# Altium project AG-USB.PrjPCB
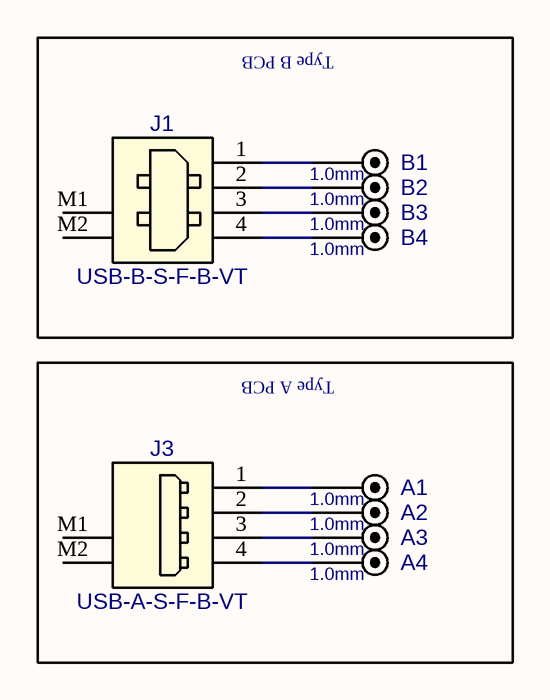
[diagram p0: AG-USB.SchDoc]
PCB_Company Name: AGRIGEL; PCB_DocRevision: 01; PCB_Drawing Number: -; PCB_Drawn: EDM; PCB_ECRNo: -; PCB_Plot File: AG-USB [Panel]; PCB_Plot File [Assy]: AG-USB [Assy]; PCB_TITLE: AG USB PCB; PRINT_DATE: 03/04/2013; SCH_Approved: DG; SCH_CM: -; SCH_Date: 25/03/2013; SCH_DocRev: 01; SCH_DRAWN: DG; SCH_ECR: -; SCH_FILENAME: AG-USB.SCH; SCH_Number: -; SCH_QA: -; SCH_Reviewed: DG; SCH_SheetTotal: 1; SCH_Title: AG USB; Version: 01.00
1 sheet, 10 parts. Net scope: global (net labels, ports and power ports of the same name join across sheets).
Board files: AG-USB.PcbDoc, AG-USB [Assy].PcbDoc, AG-USB [Panel].PcbDoc

## Sheet AG-USB.SchDoc: #
size A3; ApprovedBy: #; DrawnBy: #; DocumentNumber: 6; Revision: #; SheetNumber: 1; DocumentRevision: #; Reviewed: #; QA: #; CM: #; ECR: #; PageSetup: Record=PageOptions|CenterHorizontal=True|CenterVertical=True|PrintScale=0.97|XCorrection=1.00|YCorrection=1.00|PrintKind=1|BorderSize=5000000|LeftOffset=0|BottomOffset=0|Orientation=2|PaperLength=1000|PaperWidth=1000|Scale=100|PaperSource=7|PrintQuality=-4|MediaType=1|DitherType=10|PaperKind=A3|PrintScaleMode=1

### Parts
A1  Part Number: 1.0mm  [TP-THP-1.0mm]  (hidden comment: Hole-1.5x3.0mm)  (no BOM)
A2  Part Number: 1.0mm  [TP-THP-1.0mm]  (hidden comment: Hole-1.5x3.0mm)  (no BOM)
A3  Part Number: 1.0mm  [TP-THP-1.0mm]  (hidden comment: Hole-1.5x3.0mm)  (no BOM)
A4  Part Number: 1.0mm  [TP-THP-1.0mm]  (hidden comment: Hole-1.5x3.0mm)  (no BOM)
B1  Part Number: 1.0mm  [TP-THP-1.0mm]  (hidden comment: Hole-1.5x3.0mm)  (no BOM)
B2  Part Number: 1.0mm  [TP-THP-1.0mm]  (hidden comment: Hole-1.5x3.0mm)  (no BOM)
B3  Part Number: 1.0mm  [TP-THP-1.0mm]  (hidden comment: Hole-1.5x3.0mm)  (no BOM)
B4  Part Number: 1.0mm  [TP-THP-1.0mm]  (hidden comment: Hole-1.5x3.0mm)  (no BOM)
J1  USB-B-S-F-B-VT  [USB-B-S-X-X-VT]
J3  USB-A-S-F-B-VT  [USB-A-S-X-X-VT-X]

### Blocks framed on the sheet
Type B PCB: B1-B4 J1
Type A PCB: A1-A4 J3

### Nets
NetA1_1: A1.1 J3.1
NetA2_1: A2.1 J3.2
NetA3_1: A3.1 J3.3
NetA4_1: A4.1 J3.4
NetB1_1: B1.1 J1.1
NetB2_1: B2.1 J1.2
NetB3_1: B3.1 J1.3
NetB4_1: B4.1 J1.4

Not connected (* = marked no-connect by the designer): J1 M1 M2; J3 M1 M2

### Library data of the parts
A1-A4 B1-B4 = Hole-1.0mm_H: Hole 1.0mm; Manufacturer: Generic; Board Tech: THP
J1 = USB-B-S-F-B-VT: Connector USB B Vertical Top Entry; Manufacturer: SAMTEC; Board Tech: THP
J3 = USB-A-S-F-B-VT: Connector USB A Vertical Top Entry; Manufacturer: SAMTEC; Board Tech: THP; Value: USB-AB-S-F-B-VT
